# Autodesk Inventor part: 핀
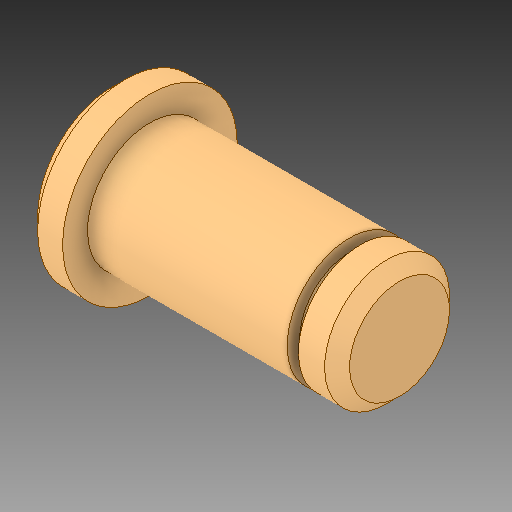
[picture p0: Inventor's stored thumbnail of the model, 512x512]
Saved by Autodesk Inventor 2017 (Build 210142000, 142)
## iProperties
Created: 2024-08
Part Number: 핀
Material: 일반
Document SubType Name: Modeling
Designer: MRC
Density: 1 g/cm^3
Appearance: 기본값
Author: jhkim
Sending System: Autodesk Inventor 2025
Preprocessor: ST-DEVELOPER v20
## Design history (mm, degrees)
feature "솔리드1"
node "솔리드2"
